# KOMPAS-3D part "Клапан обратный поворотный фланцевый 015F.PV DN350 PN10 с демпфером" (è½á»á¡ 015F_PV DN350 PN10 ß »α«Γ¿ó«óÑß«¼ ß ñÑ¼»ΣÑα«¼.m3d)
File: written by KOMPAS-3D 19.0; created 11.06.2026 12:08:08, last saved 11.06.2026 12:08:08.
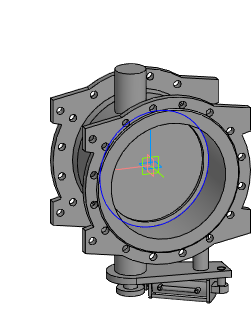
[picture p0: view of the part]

Document properties: Автор: Энергия; Полное имя файла: Z:\3.Личные\kachalov\001_3d для проектировщиков\5.5 Тип 015F.PV Клапан обратный поворотный с двумя эксцентриками\_stp_Клапан 015F.PV DN300-DN1200 с противовесом с демпфером\Клапан 015F_PV DN350 PN10 с противовесом с демпфером.m3d

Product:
- Part/product: Клапан обратный поворотный фланцевый 015F.PV DN350 PN10 с демпфером

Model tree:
1. Операция без истории:1
2. Сплайн:1
     Координата Y = 30; Координата Z = 175; Вес = 1; Координата X = 350; Координата Y = 76.0784; Координата Z = 175; Вес = 0.333333; Координата X = 350; Координата Y = 76.0784; Координата Z = -175; Вес = 0.333333; Координата Y = 30; Координата Z = -175; Вес = 1; Координата X = -350; Координата Y = -16.0784; Координата Z = -175; Вес = 0.333333; Координата X = -350; Координата Y = -16.0784; Координата Z = 175; Вес = 0.333333; Порядок = 4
